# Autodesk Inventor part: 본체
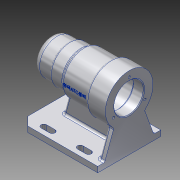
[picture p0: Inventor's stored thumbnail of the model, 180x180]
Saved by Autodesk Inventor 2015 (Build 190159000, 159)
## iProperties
Created: 2017-09
Part Number: 본체
Material: 알루미늄 6061
Document SubType Name: Modeling
Designer: owner
Density: 2.7 g/cm^3
Appearance: 알루미늄 - 평지
Mass: 692.85 g
Surface Area: 710.882 cm^2
Volume: 256.611 cm^3
Author: owner
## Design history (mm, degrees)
sketch "스케치1"
  geometry: L1 (-56, 0)-(56, 0); L2 (-56, 0)-(-56, 25); L3 (-56, 25)-(-31, 25); L4 (-31, 25)-(-31, 27); L5 (-31, 27)-(-11, 27); L6 (-11, 27)-(-11, 30); L7 (-11, 30)-(28, 30); L8 (28, 30)-(28, 34); L9 (28, 34)-(56, 34); L10 (56, 34)-(56, 0); 2 further points
  constraints: 20 end point, 8 perpendicular, 1 coincident, 1 horizontal, 1 midpoint, 1 vertical
  dimensions: "d0" = 112 distance of L1.start L1.end; "d1" = 50 diameter of L3 L1; "d2" = 54 diameter of L5 L1; "d3" = 60 diameter of L7 L1; "d4" = 68 diameter of L9 L1; "d5" = 25 distance of L2.end L3.end; "d6" = 45 distance between parallel lines of L6 L2; "d7" = 84 distance between parallel lines of L8 L2
revolve "회전1" sketch "스케치1" stored, may be unused: angle "d8" = 90 deg
fillet "모깎기1" dims "d9" = 9
sketch "스케치2"
  geometry: L1 (-56, -16)-(-56, 16) reference; L2 (56, -34)-(56, 34) reference; L3 (-56, 0)-(56, 0); L4 (-50, 0)-(-50, 10.5); L5 (-50, 10.5)-(-47, 10.5); L6 (-47, 10.5)-(-47, 16); L7 (-47, 16)-(-43, 16); L8 (-43, 16)-(-43, 17.5); L9 (-43, 17.5)-(-25, 17.5); L10 (-25, 17.5)-(-25, 21); L11 (-25, 21)-(-13, 21); L12 (-13, 21)-(-13, 24); L13 (-13, 24)-(41, 24); L14 (41, 24)-(41, 21); L15 (41, 21)-(56, 21); L16 (56, 21)-(56, 0); 1 further point
  constraints: 28 end point, 10 perpendicular, 4 point on line, 2 midpoint, 1 horizontal, 1 vertical
  dimensions: "d10" = 21 diameter of L5 L3; "d11" = 32 diameter of L7 L3; "d12" = 35 diameter of L9 L3; "d13" = 42 diameter of L11 L3; "d14" = 48 diameter of L13 L3; "d15" = 3 distance of L4.end L5.end; "d16" = 4 distance of L6.end L7.end; "d17" = 18 distance of L8.end L9.end; "d18" = 12 distance of L10.end L11.end; "d19" = 54 distance of L12.end L13.end; "d20" = 15 distance of L14.end L15.end
revolve "회전2" sketch "스케치2" stored, may be unused: angle "d21" = 90 deg
fillet "모깎기2" dims "d22" = 3
fillet "모깎기3" dims "d23" = 0.3
chamfer "모따기1" distance "d24" = 1; stored, may be unused: second distance "d25" = 2, angle "d26" = 45 deg
sketch "스케치3" dims "d27" = 52
  geometry: C1 r 22 at (0, 0) reference; 2 further points
  constraints: 1 coincident, 1 vertical alignment, 2 other
hole "구멍1" sketch "스케치3" at (0, 26) diameter "d28" = 3.242; stored, may be unused: countersink angle "d32" = 90 deg, drill point angle "d34" = 118 deg; dims "d29" = 8, "d30" = 4, "d31" = 2, "d33" = 11
node "작업 평면1"
sketch "스케치4"
  geometry: L1 (56, 45)-(-56, 45); L2 (-56, 45)-(-56, -45); L3 (-56, -45)-(56, -45); L4 (56, -45)-(56, 45); L5 (56, 45)-(-56, -45); L6 (-56, 45)-(56, -45); 1 further point
  constraints: 12 end point, 2 midpoint, 2 parallel, 1 horizontal, 1 perpendicular
  dimensions: "d39" = 112 distance of L3.end L2.end; "d40" = 90 distance of L2.end L1.end
extrude "돌출1" join sketch "스케치4" distance "d41" = 8; taper "d42" = 0 deg
sketch "스케치6"
  geometry: L1 (0, 8)-(90, 8) reference; L2 (0, 0)-(0, 8) reference; L3 (23.1, 43.992)-(10, 8); L4 (10, 8)-(80, 8); L5 (80, 8)-(66.9, 43.992); A1 r 34 centre (45, 70) between (23.1, 43.992) and (66.9, 43.992) reference; A2 r 34 centre (45, 70) between (23.1, 43.992) and (66.9, 43.992); 2 further points
  constraints: 6 end point, 4 point on circle, 2 point on line, 1 centre point, 1 coincident, 1 midpoint, 1 vertical alignment
  dimensions: "d51" = 10 distance from line of L2 L3.end; "d52" = 110 deg angle of L1 L5; "d53" = 110 deg angle of L1 L3
extrude "돌출3" join sketch "스케치6" distance "d54" = 8; taper "d55" = 0 deg
sketch "스케치7"
  geometry: L1 (-56, 45)-(-56, -45) reference; L2 (56, -4)-(-34, -4); L3 (-34, -4)-(-34, 4); L4 (-34, 4)-(56, 4); L5 (56, 4)-(56, -4); L6 (56, -45)-(56, 45) reference; 2 further points
  constraints: 8 end point, 2 parallel, 1 collinear, 1 horizontal, 1 horizontal alignment, 1 midpoint, 1 perpendicular
  dimensions: "d56" = 22 distance between parallel lines of L3 L1; "d57" = 8 distance of L2.end L3.end
extrude "돌출4" join sketch "스케치7" stored distance "d58" = 8; taper "d59" = 0 deg
feature "면 기울기2" dims angle "d60" = 15 deg
sketch "스케치8"
  geometry: L1 (-32, 34)-(-20, 34); L2 (-32, 30)-(-20, 30); L3 (-20, 38)-(-32, 38); L4 (20, 34)-(32, 34); L5 (20, 38)-(32, 38); L6 (32, 30)-(20, 30); L7 (-32, -34)-(-20, -34); L8 (-32, -30)-(-20, -30); L9 (-20, -38)-(-32, -38); L10 (32, -34)-(20, -34); L11 (32, -30)-(20, -30); L12 (20, -38)-(32, -38); L13 (56, -45)-(56, 45) reference; A1 r 4 centre (-32, 34) between (-32, 38) and (-32, 30); A2 r 4 centre (-20, 34) between (-20, 30) and (-20, 38); A3 r 4 centre (20, 34) between (20, 38) and (20, 30); A4 r 4 centre (32, 34) between (32, 30) and (32, 38); A5 r 4 centre (-32, -34) between (-32, -30) and (-32, -38); A6 r 4 centre (-20, -34) between (-20, -38) and (-20, -30); A7 r 4 centre (32, -34) between (32, -38) and (32, -30); A8 r 4 centre (20, -34) between (20, -30) and (20, -38); 5 further points
  constraints: 32 end point, 16 point on circle, 16 tangent, 8 centre point, 5 parallel, 4 midpoint, 2 horizontal, 2 point on line
  dimensions: "d61" = 4 radius of A1; "d62" = 24 distance from line of L10.start L13; "d63" = 12 distance of L10.end L10.start; "d64" = 40 distance of L7.end L10.end; "d65" = 12 distance of L7.end L7.start; "d66" = 24 distance from line of L13 L4.end; "d67" = 12 distance of L4.start L4.end; "d68" = 40 distance of L1.end L4.start; "d69" = 12 distance of L1.start L1.end; "d70" = 34 vertical distance of point (-26, 34) point (0, 0); "d71" = 34 vertical distance of point (0, 0) point (26, 34); "d72" = 34 vertical distance of point (0, 0) point (-26, -34); "d73" = 4 radius of A3; "d74" = 4 radius of A5; "d75" = 4 radius of A8
extrude "돌출5" cut sketch "스케치8" stored distance "d76" = 0; taper "d77" = 0 deg
fillet "모깎기4" dims "d78" = 3
fillet "모깎기5" dims "d79" = 3
fillet "모깎기6" dims "d80" = 3
fillet "모깎기7" dims "d81" = 3
fillet "모깎기8" dims "d82" = 3
chamfer "모따기2" distance "d83" = 12; stored, may be unused: second distance "d84" = 12, angle "d85" = 45 deg
chamfer "모따기3" distance "d86" = 12; stored, may be unused: second distance "d87" = 12, angle "d88" = 45 deg
node "작업 평면2"
node "작업 평면3"
sketch "스케치10"
  geometry: L1 (56, -24.711)-(56, 34) reference; 2 further points
  constraints: 1 horizontal alignment, 1 other
  dimensions: "d94" = 48 distance from line of point (8, 0) L1
feature "엠보싱2" sketch "스케치10" dims "d10" = 21, "d11" = 32, "d12" = 35, "d13" = 42, "d14" = 48, "d15" = 3, "d16" = 4, "d17" = 18, "d18" = 12, "d19" = 54, "d20" = 15, "d95" = 0.5, "d96" = 0
node "솔리드1"
pattern_circular "원형 패턴1" dims angle "d36" = 360 deg
other parameters: "d89" = -69.75, "d93" = 132.25
